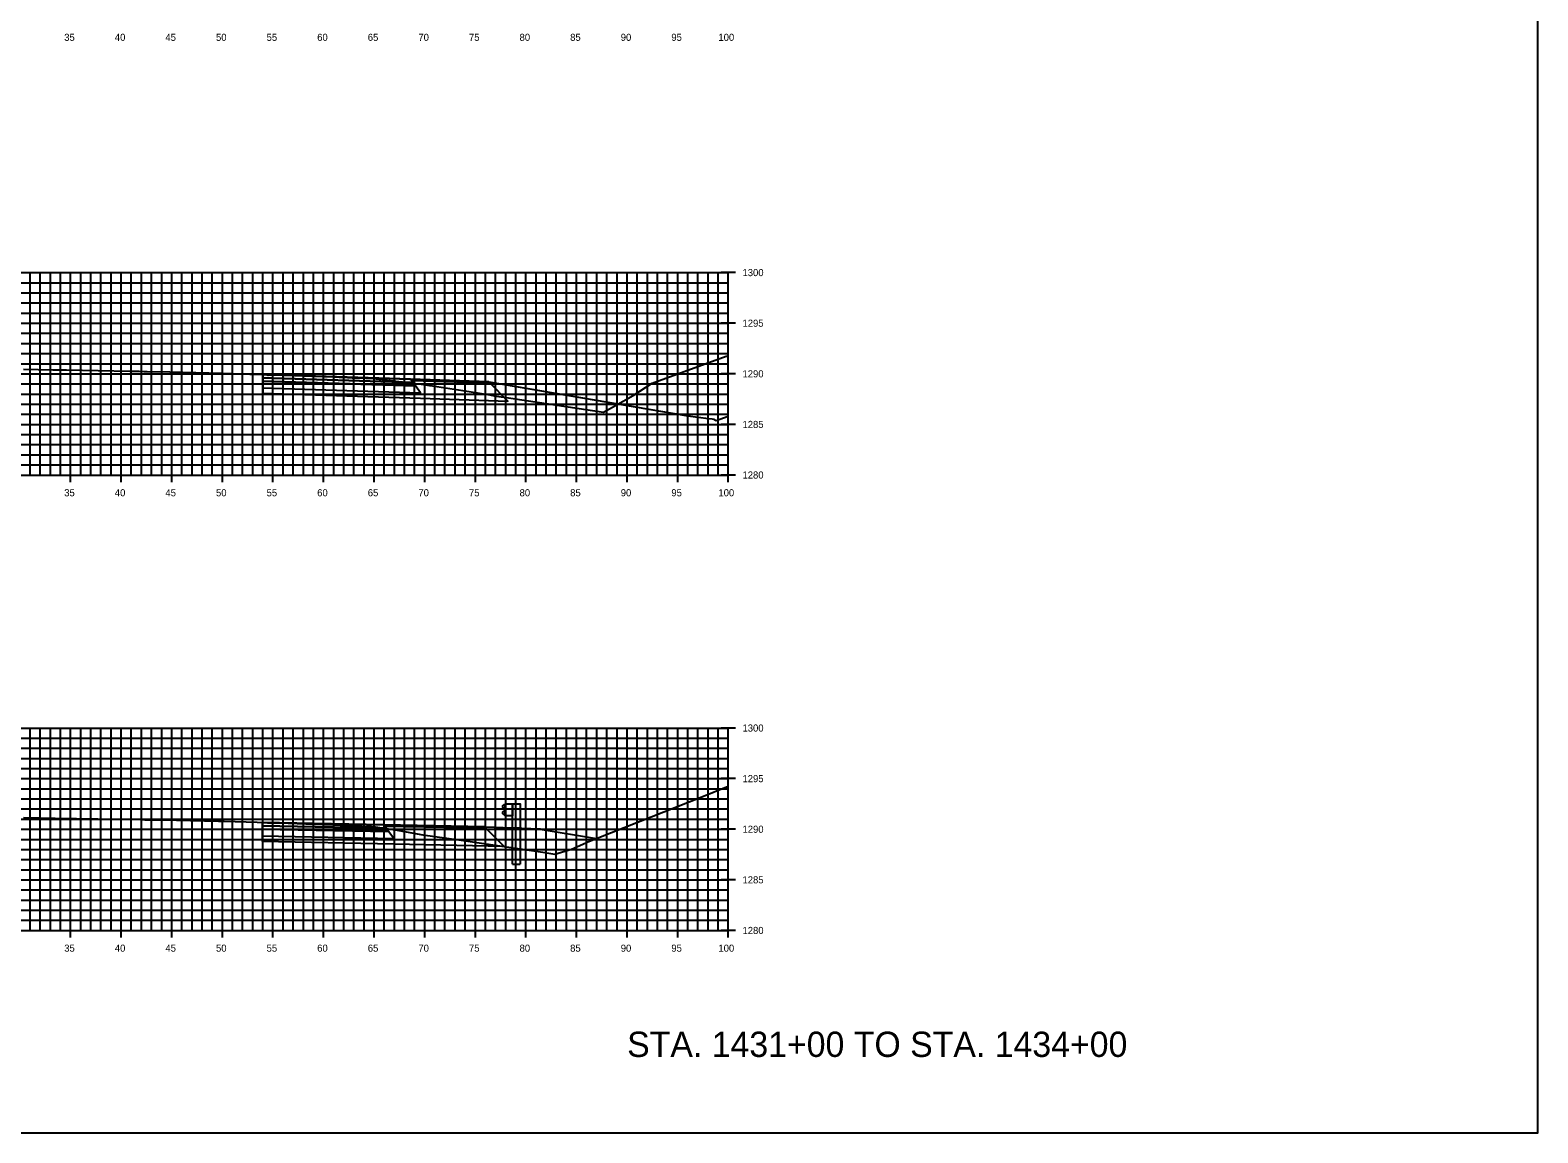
# Model space of a CAD drawing. Extents: x 674939 to 678919, y 750652 to 765176.
# Drawn here: x 677969.5 to 678118.5, y 758282.6 to 758391.5 of the extents above; entities that cross this region are included whole.
import ezdxf

# ---------------------------------------------------------------- set-up
doc = ezdxf.new("R2010")
doc.units = 0
for name, color, linetype in [('R_Alt Surface', 7, 'Continuous'), ('R_Axis', 7, 'Continuous'), ('R_Axis Annot', 7, 'Continuous'), ('R_Draft', 7, 'Continuous'), ('R_Exist Surface', 7, 'Continuous'), ('R_Fin Surface', 7, 'Continuous'), ('R_Grid', 7, 'Continuous'), ('R_No Plot', 7, 'Continuous')]:
    doc.layers.add(name, color=color, linetype=linetype)

msp = doc.modelspace()

# ---------------------------------------------------------------- linework, layer by layer
msp.add_lwpolyline([(678019.93, 758312.58), (678019.94, 758312.57), (678019.94, 758312.57), (678025.51, 758311.65)])
at = {"layer": 'R_Alt Surface'}
for points in [[(677992.53, 758357.16), (677992.53, 758356.83), (678007.62, 758356.35), (678007.37, 758356.68)], [(677992.53, 758356.83), (677992.53, 758356.17), (678008.12, 758355.68), (678007.62, 758356.35)], [(677992.46, 758312.9), (677992.46, 758312.57), (678004.96, 758312.32), (678004.71, 758312.65)], [(677992.46, 758312.57), (677992.46, 758311.91), (678005.46, 758311.65), (678004.96, 758312.32)]]:
    msp.add_lwpolyline(points, close=True, dxfattribs=at)
for points in [[(677992.53, 758356.17), (677992.53, 758355.63), (678008.12, 758355.14), (678016.74, 758354.86), (678014.99, 758356.61)], [(677992.46, 758311.91), (677992.46, 758311.37), (678005.46, 758311.11), (678016.33, 758310.89), (678014.58, 758312.64)]]:
    msp.add_lwpolyline(points, dxfattribs=at)
at = {"layer": 'R_Axis'}
for p, q in [((678039.23, 758367.55), (678037.83, 758367.55)), ((678038.53, 758347.55), (678038.53, 758367.55)), ((678039.23, 758362.55), (678037.83, 758362.55)), ((678039.23, 758357.55), (678037.83, 758357.55)), ((678039.23, 758352.55), (678037.83, 758352.55)), ((677973.53, 758346.85), (677973.53, 758348.25)), ((677978.53, 758346.85), (677978.53, 758348.25)), ((677983.53, 758346.85), (677983.53, 758348.25)), ((677988.53, 758346.85), (677988.53, 758348.25)), ((677993.53, 758346.85), (677993.53, 758348.25)), ((677998.53, 758346.85), (677998.53, 758348.25)), ((678003.53, 758346.85), (678003.53, 758348.25)), ((678008.53, 758346.85), (678008.53, 758348.25)), ((678013.53, 758346.85), (678013.53, 758348.25)), ((678018.53, 758346.85), (678018.53, 758348.25)), ((678023.53, 758346.85), (678023.53, 758348.25)), ((678028.53, 758346.85), (678028.53, 758348.25)), ((678033.53, 758346.85), (678033.53, 758348.25)), ((678038.53, 758346.85), (678038.53, 758348.25)), ((677838.53, 758347.55), (678038.53, 758347.55)), ((678039.23, 758347.55), (678037.83, 758347.55)), ((678039.23, 758322.55), (678037.83, 758322.55)), ((678038.53, 758302.55), (678038.53, 758322.55)), ((678039.23, 758317.55), (678037.83, 758317.55)), ((678039.23, 758312.55), (678037.83, 758312.55)), ((678039.23, 758307.55), (678037.83, 758307.55)), ((677838.53, 758302.55), (678038.53, 758302.55)), ((677973.53, 758301.85), (677973.53, 758303.25)), ((677978.53, 758301.85), (677978.53, 758303.25)), ((677983.53, 758301.85), (677983.53, 758303.25)), ((677988.53, 758301.85), (677988.53, 758303.25)), ((677993.53, 758301.85), (677993.53, 758303.25)), ((677998.53, 758301.85), (677998.53, 758303.25)), ((678003.53, 758301.85), (678003.53, 758303.25)), ((678008.53, 758301.85), (678008.53, 758303.25)), ((678013.53, 758301.85), (678013.53, 758303.25)), ((678018.53, 758301.85), (678018.53, 758303.25)), ((678023.53, 758301.85), (678023.53, 758303.25)), ((678028.53, 758301.85), (678028.53, 758303.25)), ((678033.53, 758301.85), (678033.53, 758303.25)), ((678039.23, 758302.55), (678037.83, 758302.55)), ((678038.53, 758301.85), (678038.53, 758303.25))]:
    msp.add_line(p, q, dxfattribs=at)
at = {"layer": 'R_Exist Surface'}
for points in [[(677968.86, 758358.01), (677971.78, 758357.95), (677973.12, 758357.93), (677979.39, 758357.82), (677980.29, 758357.8), (677980.77, 758357.77), (677980.85, 758357.77), (677981.08, 758357.77), (677983.34, 758357.74), (677984.63, 758357.71), (677988.49, 758357.62), (677991.23, 758357.53), (677991.98, 758357.51), (677992.47, 758357.5), (677992.53, 758357.49), (677992.56, 758357.49), (677992.97, 758357.44), (677993.05, 758357.43), (677994.34, 758357.44), (677994.69, 758357.44), (677995.08, 758357.43), (677997.33, 758357.33), (677997.37, 758357.34), (677997.61, 758357.32), (677999.54, 758357.24), (678000.08, 758357.22), (678000.41, 758357.22), (678001.37, 758357.16), (678001.41, 758357.16), (678001.57, 758357.15), (678002.69, 758357.11), (678002.97, 758357.11), (678003.29, 758357.11), (678003.45, 758357.08), (678003.48, 758357.09), (678008.17, 758356.52), (678008.61, 758356.46), (678009.01, 758356.4), (678009.3, 758356.35), (678012.28, 758355.89), (678014.95, 758355.46), (678015.4, 758355.38), (678017.05, 758355.14), (678026.2, 758353.76), (678027.37, 758354.41), (678029.13, 758355.4), (678031, 758356.62), (678034.17, 758357.79), (678038.32, 758359.29), (678038.53, 758359.29)], [(677968.88, 758313.7), (677970.43, 758313.67), (677970.71, 758313.66), (677972, 758313.64), (677980.45, 758313.51), (677980.54, 758313.51), (677980.88, 758313.48), (677981.02, 758313.48), (677982.23, 758313.49), (677982.61, 758313.48), (677988.13, 758313.35), (677988.71, 758313.34), (677991.97, 758313.25), (677992.46, 758313.23), (677992.48, 758313.23), (677992.48, 758313.23), (677993, 758313.18), (677993.11, 758313.17), (677993.97, 758313.18), (677994.19, 758313.18), (677998.51, 758313.03), (677999.03, 758313.01), (677999.44, 758312.99), (678003.06, 758312.83), (678003.28, 758312.82), (678003.58, 758312.79), (678003.64, 758312.79), (678003.65, 758312.79), (678005.61, 758312.48), (678008.33, 758312.01), (678011.89, 758311.49), (678020.19, 758310.28), (678021.37, 758310.09), (678023.04, 758310.59), (678024.45, 758311.21), (678024.48, 758311.24), (678024.49, 758311.24), (678035.9, 758315.76), (678038.53, 758316.8)]]:
    msp.add_lwpolyline(points, dxfattribs=at)
at = {"layer": 'R_Fin Surface'}
for points in [[(678014.87, 758356.77), (678007.12, 758357.02), (677992.53, 758357.49)], [(678014.87, 758356.77), (678014.87, 758356.77)], [(678014.46, 758312.79), (678004.46, 758312.99), (677992.46, 758313.23)], [(678014.46, 758312.79), (678019.93, 758312.58)]]:
    msp.add_lwpolyline(points, dxfattribs=at)
for points in [[(677992.53, 758357.49), (677992.53, 758357.16), (678007.37, 758356.68), (678007.12, 758357.02)], [(678007.12, 758357.02), (678014.87, 758356.77), (678014.99, 758356.61), (678007.24, 758356.86)], [(677992.46, 758313.23), (677992.46, 758312.9), (678004.71, 758312.65), (678004.46, 758312.99)], [(678004.46, 758312.99), (678014.46, 758312.79), (678014.58, 758312.64), (678004.57, 758312.83)]]:
    msp.add_lwpolyline(points, close=True, dxfattribs=at)
at = {"layer": 'R_Grid'}
for p, q in [((677838.53, 758367.55), (678038.53, 758367.55)), ((677969.53, 758347.55), (677969.53, 758367.55)), ((677970.53, 758347.55), (677970.53, 758367.55)), ((677971.53, 758347.55), (677971.53, 758367.55)), ((677972.53, 758347.55), (677972.53, 758367.55)), ((677973.53, 758347.55), (677973.53, 758367.55)), ((677974.53, 758347.55), (677974.53, 758367.55)), ((677975.53, 758347.55), (677975.53, 758367.55)), ((677976.53, 758347.55), (677976.53, 758367.55)), ((677977.53, 758347.55), (677977.53, 758367.55)), ((677978.53, 758347.55), (677978.53, 758367.55)), ((677979.53, 758347.55), (677979.53, 758367.55)), ((677980.53, 758347.55), (677980.53, 758367.55)), ((677981.53, 758347.55), (677981.53, 758367.55)), ((677982.53, 758347.55), (677982.53, 758367.55)), ((677983.53, 758347.55), (677983.53, 758367.55)), ((677984.53, 758347.55), (677984.53, 758367.55)), ((677985.53, 758347.55), (677985.53, 758367.55)), ((677986.53, 758347.55), (677986.53, 758367.55)), ((677987.53, 758347.55), (677987.53, 758367.55)), ((677988.53, 758347.55), (677988.53, 758367.55)), ((677989.53, 758347.55), (677989.53, 758367.55)), ((677990.53, 758347.55), (677990.53, 758367.55)), ((677991.53, 758347.55), (677991.53, 758367.55)), ((677992.53, 758347.55), (677992.53, 758367.55)), ((677993.53, 758347.55), (677993.53, 758367.55)), ((677994.53, 758347.55), (677994.53, 758367.55)), ((677995.53, 758347.55), (677995.53, 758367.55)), ((677996.53, 758347.55), (677996.53, 758367.55)), ((677997.53, 758347.55), (677997.53, 758367.55)), ((677998.53, 758347.55), (677998.53, 758367.55)), ((677999.53, 758347.55), (677999.53, 758367.55)), ((678000.53, 758347.55), (678000.53, 758367.55)), ((678001.53, 758347.55), (678001.53, 758367.55)), ((678002.53, 758347.55), (678002.53, 758367.55)), ((678003.53, 758347.55), (678003.53, 758367.55)), ((678004.53, 758347.55), (678004.53, 758367.55)), ((678005.53, 758347.55), (678005.53, 758367.55)), ((678006.53, 758347.55), (678006.53, 758367.55)), ((678007.53, 758347.55), (678007.53, 758367.55)), ((678008.53, 758347.55), (678008.53, 758367.55)), ((678009.53, 758347.55), (678009.53, 758367.55)), ((678010.53, 758347.55), (678010.53, 758367.55)), ((678011.53, 758347.55), (678011.53, 758367.55)), ((678012.53, 758347.55), (678012.53, 758367.55)), ((678013.53, 758347.55), (678013.53, 758367.55)), ((678014.53, 758347.55), (678014.53, 758367.55)), ((678015.53, 758347.55), (678015.53, 758367.55)), ((678016.53, 758347.55), (678016.53, 758367.55)), ((678017.53, 758347.55), (678017.53, 758367.55)), ((678018.53, 758347.55), (678018.53, 758367.55)), ((678019.53, 758347.55), (678019.53, 758367.55)), ((678020.53, 758347.55), (678020.53, 758367.55)), ((678021.53, 758347.55), (678021.53, 758367.55)), ((678022.53, 758347.55), (678022.53, 758367.55)), ((678023.53, 758347.55), (678023.53, 758367.55)), ((678024.53, 758347.55), (678024.53, 758367.55)), ((678025.53, 758347.55), (678025.53, 758367.55)), ((678026.53, 758347.55), (678026.53, 758367.55)), ((678027.53, 758347.55), (678027.53, 758367.55)), ((678028.53, 758347.55), (678028.53, 758367.55)), ((678029.53, 758347.55), (678029.53, 758367.55)), ((678030.53, 758347.55), (678030.53, 758367.55)), ((678031.53, 758347.55), (678031.53, 758367.55)), ((678032.53, 758347.55), (678032.53, 758367.55)), ((678033.53, 758347.55), (678033.53, 758367.55)), ((678034.53, 758347.55), (678034.53, 758367.55)), ((678035.53, 758347.55), (678035.53, 758367.55)), ((678036.53, 758347.55), (678036.53, 758367.55)), ((678037.53, 758347.55), (678037.53, 758367.55)), ((678038.53, 758347.55), (678038.53, 758367.55)), ((677838.53, 758366.55), (678038.53, 758366.55)), ((677838.53, 758365.55), (678038.53, 758365.55)), ((677838.53, 758364.55), (678038.53, 758364.55)), ((677838.53, 758363.55), (678038.53, 758363.55)), ((677838.53, 758362.55), (678038.53, 758362.55)), ((677838.53, 758361.55), (678038.53, 758361.55)), ((677838.53, 758360.55), (678038.53, 758360.55)), ((677838.53, 758359.55), (678038.53, 758359.55)), ((677838.53, 758358.55), (678038.53, 758358.55)), ((677838.53, 758357.55), (678038.53, 758357.55)), ((677838.53, 758356.55), (678038.53, 758356.55)), ((677838.53, 758355.55), (678038.53, 758355.55)), ((677838.53, 758354.55), (678038.53, 758354.55)), ((677838.53, 758353.55), (678038.53, 758353.55)), ((677838.53, 758352.55), (678038.53, 758352.55)), ((677838.53, 758351.55), (678038.53, 758351.55)), ((677838.53, 758350.55), (678038.53, 758350.55)), ((677838.53, 758349.55), (678038.53, 758349.55)), ((677838.53, 758348.55), (678038.53, 758348.55)), ((677838.53, 758347.55), (678038.53, 758347.55)), ((677838.53, 758322.55), (678038.53, 758322.55)), ((677838.53, 758321.55), (678038.53, 758321.55)), ((677969.53, 758302.55), (677969.53, 758322.55)), ((677970.53, 758302.55), (677970.53, 758322.55)), ((677971.53, 758302.55), (677971.53, 758322.55)), ((677972.53, 758302.55), (677972.53, 758322.55)), ((677973.53, 758302.55), (677973.53, 758322.55)), ((677974.53, 758302.55), (677974.53, 758322.55)), ((677975.53, 758302.55), (677975.53, 758322.55)), ((677976.53, 758302.55), (677976.53, 758322.55)), ((677977.53, 758302.55), (677977.53, 758322.55)), ((677978.53, 758302.55), (677978.53, 758322.55)), ((677979.53, 758302.55), (677979.53, 758322.55)), ((677980.53, 758302.55), (677980.53, 758322.55)), ((677981.53, 758302.55), (677981.53, 758322.55)), ((677982.53, 758302.55), (677982.53, 758322.55)), ((677983.53, 758302.55), (677983.53, 758322.55)), ((677984.53, 758302.55), (677984.53, 758322.55)), ((677985.53, 758302.55), (677985.53, 758322.55)), ((677986.53, 758302.55), (677986.53, 758322.55)), ((677987.53, 758302.55), (677987.53, 758322.55)), ((677988.53, 758302.55), (677988.53, 758322.55)), ((677989.53, 758302.55), (677989.53, 758322.55)), ((677990.53, 758302.55), (677990.53, 758322.55)), ((677991.53, 758302.55), (677991.53, 758322.55)), ((677992.53, 758302.55), (677992.53, 758322.55)), ((677993.53, 758302.55), (677993.53, 758322.55)), ((677994.53, 758302.55), (677994.53, 758322.55)), ((677995.53, 758302.55), (677995.53, 758322.55)), ((677996.53, 758302.55), (677996.53, 758322.55)), ((677997.53, 758302.55), (677997.53, 758322.55)), ((677998.53, 758302.55), (677998.53, 758322.55)), ((677999.53, 758302.55), (677999.53, 758322.55)), ((678000.53, 758302.55), (678000.53, 758322.55)), ((678001.53, 758302.55), (678001.53, 758322.55)), ((678002.53, 758302.55), (678002.53, 758322.55)), ((678003.53, 758302.55), (678003.53, 758322.55)), ((678004.53, 758302.55), (678004.53, 758322.55)), ((678005.53, 758302.55), (678005.53, 758322.55)), ((678006.53, 758302.55), (678006.53, 758322.55)), ((678007.53, 758302.55), (678007.53, 758322.55)), ((678008.53, 758302.55), (678008.53, 758322.55)), ((678009.53, 758302.55), (678009.53, 758322.55)), ((678010.53, 758302.55), (678010.53, 758322.55)), ((678011.53, 758302.55), (678011.53, 758322.55)), ((678012.53, 758302.55), (678012.53, 758322.55)), ((678013.53, 758302.55), (678013.53, 758322.55)), ((678014.53, 758302.55), (678014.53, 758322.55)), ((678015.53, 758302.55), (678015.53, 758322.55)), ((678016.53, 758302.55), (678016.53, 758322.55)), ((678017.53, 758302.55), (678017.53, 758322.55)), ((678018.53, 758302.55), (678018.53, 758322.55)), ((678019.53, 758302.55), (678019.53, 758322.55)), ((678020.53, 758302.55), (678020.53, 758322.55)), ((678021.53, 758302.55), (678021.53, 758322.55)), ((678022.53, 758302.55), (678022.53, 758322.55)), ((678023.53, 758302.55), (678023.53, 758322.55)), ((678024.53, 758302.55), (678024.53, 758322.55)), ((678025.53, 758302.55), (678025.53, 758322.55)), ((678026.53, 758302.55), (678026.53, 758322.55)), ((678027.53, 758302.55), (678027.53, 758322.55)), ((678028.53, 758302.55), (678028.53, 758322.55)), ((678029.53, 758302.55), (678029.53, 758322.55)), ((678030.53, 758302.55), (678030.53, 758322.55)), ((678031.53, 758302.55), (678031.53, 758322.55)), ((678032.53, 758302.55), (678032.53, 758322.55)), ((678033.53, 758302.55), (678033.53, 758322.55)), ((678034.53, 758302.55), (678034.53, 758322.55)), ((678035.53, 758302.55), (678035.53, 758322.55)), ((678036.53, 758302.55), (678036.53, 758322.55)), ((678037.53, 758302.55), (678037.53, 758322.55)), ((678038.53, 758302.55), (678038.53, 758322.55)), ((677838.53, 758320.55), (678038.53, 758320.55)), ((677838.53, 758319.55), (678038.53, 758319.55)), ((677838.53, 758318.55), (678038.53, 758318.55)), ((677838.53, 758317.55), (678038.53, 758317.55)), ((677838.53, 758316.55), (678038.53, 758316.55)), ((677838.53, 758315.55), (678038.53, 758315.55)), ((677838.53, 758314.55), (678038.53, 758314.55)), ((677838.53, 758313.55), (678038.53, 758313.55)), ((677838.53, 758312.55), (678038.53, 758312.55)), ((677838.53, 758311.55), (678038.53, 758311.55)), ((677838.53, 758310.55), (678038.53, 758310.55)), ((677838.53, 758309.55), (678038.53, 758309.55)), ((677838.53, 758308.55), (678038.53, 758308.55)), ((677838.53, 758307.55), (678038.53, 758307.55)), ((677838.53, 758306.55), (678038.53, 758306.55)), ((677838.53, 758305.55), (678038.53, 758305.55)), ((677838.53, 758304.55), (678038.53, 758304.55)), ((677838.53, 758303.55), (678038.53, 758303.55)), ((677838.53, 758302.55), (678038.53, 758302.55))]:
    msp.add_line(p, q, dxfattribs=at)
at = {"layer": 'R_No Plot'}
for points in [[(677778.53, 758282.55), (678118.53, 758282.55), (678118.53, 758502.55), (677778.53, 758502.55)], [(678016.46, 758315), (678016.36, 758314.97), (678016.22, 758314.87), (678016.22, 758314.73), (678016.44, 758314.53), (678016.44, 758314.44), (678016.22, 758314.24), (678016.22, 758314.09), (678016.36, 758313.99), (678016.46, 758313.97)], [(678016.46, 758315.07), (678017.21, 758315.07), (678017.21, 758313.89), (678016.46, 758313.89)], [(678017.21, 758315.07), (678017.96, 758315.07), (678017.96, 758312.65), (678017.21, 758312.68)]]:
    msp.add_lwpolyline(points, close=True, dxfattribs=at)
for points in [[(677992.53, 758357.49), (678007.06, 758357.02), (678007.12, 758357.02), (678014.8, 758356.77), (678014.87, 758356.77), (678034.53, 758353.39), (678036.58, 758353.15), (678036.94, 758353.09), (678037.13, 758353.06), (678037.14, 758353.05), (678037.32, 758352.95), (678038.53, 758353.36)], [(677992.46, 758313.23), (677992.59, 758313.23), (678004.44, 758313), (678004.46, 758312.99), (678014.43, 758312.8), (678014.46, 758312.79), (678019.91, 758312.58), (678019.93, 758312.58), (678019.94, 758312.57), (678025.49, 758311.65), (678025.51, 758311.65)], [(678017.21, 758309.1), (678017.21, 758312.68), (678017.96, 758312.65), (678017.96, 758309.1)], [(678017.21, 758309.1), (678017.96, 758309.1)]]:
    msp.add_lwpolyline(points, dxfattribs=at)

# ---------------------------------------------------------------- texts
at = {"layer": 'R_Axis Annot'}
for s, p in [('35', (677972.9, 758390.45)), ('40', (677977.9, 758390.45)), ('45', (677982.9, 758390.45)), ('50', (677987.9, 758390.45)), ('55', (677992.9, 758390.45)), ('60', (677997.9, 758390.45)), ('65', (678002.9, 758390.45)), ('70', (678007.9, 758390.45)), ('75', (678012.9, 758390.45)), ('80', (678017.9, 758390.45)), ('85', (678022.9, 758390.45)), ('90', (678027.9, 758390.45)), ('95', (678032.9, 758390.45)), ('100', (678037.55, 758390.45)), ('1300', (678039.93, 758367.2)), ('1295', (678039.93, 758362.2)), ('1290', (678039.93, 758357.2)), ('1285', (678039.93, 758352.2)), ('1280', (678039.93, 758347.2)), ('35', (677972.9, 758345.45)), ('40', (677977.9, 758345.45)), ('45', (677982.9, 758345.45)), ('50', (677987.9, 758345.45)), ('55', (677992.9, 758345.45)), ('60', (677997.9, 758345.45)), ('65', (678002.9, 758345.45)), ('70', (678007.9, 758345.45)), ('75', (678012.9, 758345.45)), ('80', (678017.9, 758345.45)), ('85', (678022.9, 758345.45)), ('90', (678027.9, 758345.45)), ('95', (678032.9, 758345.45)), ('100', (678037.55, 758345.45)), ('1300', (678039.93, 758322.2)), ('1295', (678039.93, 758317.2)), ('1290', (678039.93, 758312.2)), ('1285', (678039.93, 758307.2)), ('1280', (678039.93, 758302.2)), ('35', (677972.9, 758300.45)), ('40', (677977.9, 758300.45)), ('45', (677982.9, 758300.45)), ('50', (677987.9, 758300.45)), ('55', (677992.9, 758300.45)), ('60', (677997.9, 758300.45)), ('65', (678002.9, 758300.45)), ('70', (678007.9, 758300.45)), ('75', (678012.9, 758300.45)), ('80', (678017.9, 758300.45)), ('85', (678022.9, 758300.45)), ('90', (678027.9, 758300.45)), ('95', (678032.9, 758300.45)), ('100', (678037.55, 758300.45))]:
    msp.add_text(s, height=0.7, dxfattribs=at).set_placement(p)
at = {"layer": 'R_Draft'}
msp.add_text('STA. 1431+00 TO STA. 1434+00', height=2.5, dxfattribs=at).set_placement((678028.53, 758290.05))

doc.saveas('drawing.dxf')
